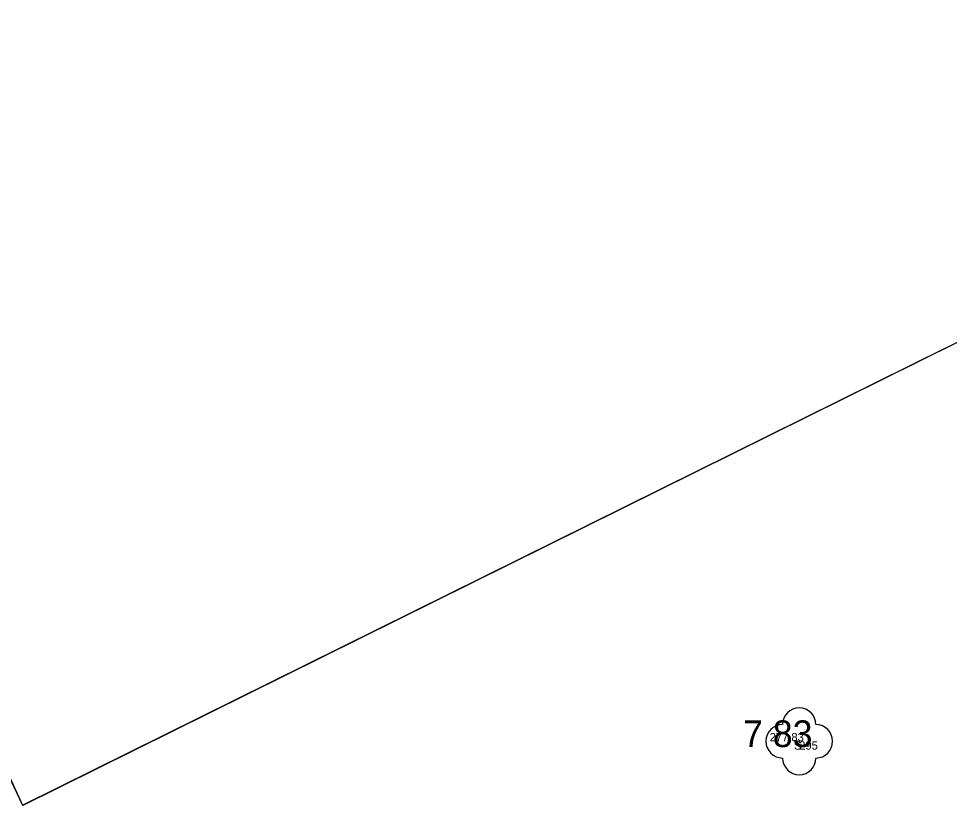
# Model space of a CAD drawing. Extents: x -601602 to -600882, y -1162594 to -1161950.
# Drawn here: x -601208.38 to -601194.43, y -1162063.99 to -1162052.2 of the extents above; entities that cross this region are included whole.
import ezdxf

# ---------------------------------------------------------------- set-up
doc = ezdxf.new("R2010")
doc.units = 0
for name, color, linetype in [('BODY', 7, 'Continuous'), ('BODY_CISLA', 7, 'Continuous'), ('BODY_KODY', 7, 'Continuous'), ('BODY_VYSKY_CELE', 7, 'Continuous'), ('G_ZELEN', 7, 'Continuous'), ('H_KOTY_VYSKOVE', 7, 'Continuous'), ('KN_Hranice parcel', 7, 'Continuous'), ('Vrstva 7', 7, 'Continuous')]:
    doc.layers.add(name, color=color, linetype=linetype)

# ---------------------------------------------------------------- blocks, each defined once
blk = doc.blocks.new('POINT_DISPLAY')
blk.add_line((0, 0), (0, 0))

msp = doc.modelspace()

# ---------------------------------------------------------------- linework, layer by layer
at = {"layer": 'G_ZELEN'}
msp.add_circle((-601196.68, -1162063.03), 0.00025, dxfattribs=at)
for centre, start, end in [((-601196.68, -1162062.78), 0, 180), ((-601196.93, -1162063.03), 90, 270), ((-601196.43, -1162063.03), 270, 90), ((-601196.68, -1162063.28), 180, 360)]:
    msp.add_arc(centre, 0.25, start, end, dxfattribs=at)
at = {"layer": 'KN_Hranice parcel'}
msp.add_lwpolyline([(-601189.34, -1162032.73), (-601190.11, -1162036.89), (-601190.25, -1162040.9), (-601189.75, -1162045.18), (-601189.25, -1162047.73), (-601188.26, -1162050.73), (-601187.02, -1162053.44), (-601208.32, -1162063.99), (-601209.9, -1162060.66), (-601211.08, -1162057.59), (-601212, -1162054.7), (-601212.73, -1162051.88), (-601213.33, -1162048.91), (-601213.84, -1162044.87), (-601214.04, -1162041.62), (-601214.04, -1162038.88), (-601213.85, -1162035.48), (-601213.49, -1162032.3)], dxfattribs=at)
at = {"layer": 'Vrstva 7'}
for p, q in [((-601208.324, -1162063.987), (-601194.481, -1162057.134)), ((-601209.898, -1162060.661), (-601208.324, -1162063.987))]:
    msp.add_line(p, q, dxfattribs=at)

# ---------------------------------------------------------------- block references
at = {"layer": 'BODY'}
msp.add_blockref('POINT_DISPLAY', (-601196.68, -1162063.03), dxfattribs=at)

# ---------------------------------------------------------------- texts
at = {"layer": 'BODY_CISLA'}
msp.add_text('295', height=0.125, dxfattribs=at).set_placement((-601196.68, -1162063.155))
at = {"layer": 'BODY_KODY'}
msp.add_text('S', height=0.125, dxfattribs=at).set_placement((-601196.761, -1162063.155))
at = {"layer": 'BODY_VYSKY_CELE'}
msp.add_text('277.83 ', height=0.125, dxfattribs=at).set_placement((-601197.123, -1162063.03))
at = {"layer": 'H_KOTY_VYSKOVE'}
msp.add_text(' 7 83', height=0.4, dxfattribs=at).set_placement((-601197.671, -1162063.116))

doc.saveas('drawing.dxf')
